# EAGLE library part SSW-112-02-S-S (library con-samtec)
THROUGH-HOLE .025" SQ POST SOCKET Source: Samtec SSW.pdf
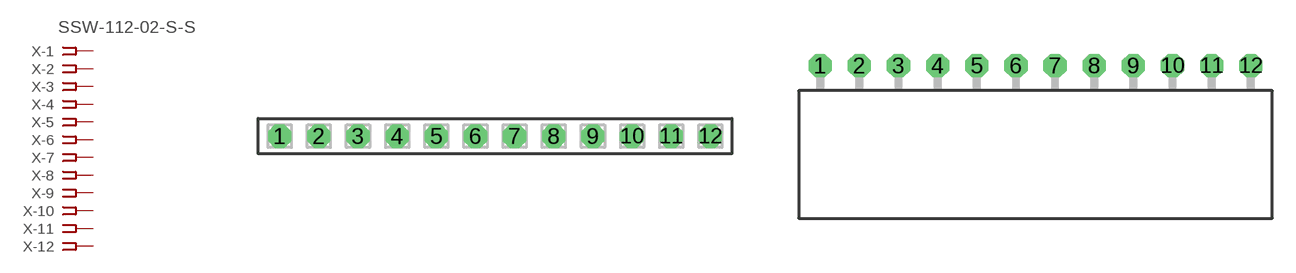
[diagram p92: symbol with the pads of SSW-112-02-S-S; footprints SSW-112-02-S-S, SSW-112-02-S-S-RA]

Designator prefix X; gates -1=FPINV -2=FPIN -3=FPIN -4=FPIN -5=FPIN -6=FPIN -7=FPIN -8=FPIN -9=FPIN -10=FPIN -11=FPIN -12=FPIN

## SSW-112-02-S-S (MPN: SSW-112-02-S-S; OC_FARNELL: unknown; OC_NEWARK: 11P9515)  [SSW-112-02-S-S]
1  -1:1  pas
2  -2:1  pas
3  -3:1  pas
4  -4:1  pas
5  -5:1  pas
6  -6:1  pas
7  -7:1  pas
8  -8:1  pas
9  -9:1  pas
10  -10:1  pas
11  -11:1  pas
12  -12:1  pas

## SSW-112-02-S-S-RA (MPN: SSW-112-02-S-S-RA; OC_FARNELL: unknown; OC_NEWARK: 11P9516)  [SSW-112-02-S-S-RA]
Pads as for SSW-112-02-S-S

## Footprint SSW-112-02-S-S (pad centres in mm)
THROUGH-HOLE .025" SQ POST SOCKET Source: Samtec SSW.pdf
drill 1 pad 1.5 octagon: 1 -13.97,0; 2 -11.43,0; 3 -8.89,0; 4 -6.35,0; 5 -3.81,0; 6 -1.27,0; 7 1.27,0; 8 3.81,0; 9 6.35,0; 10 8.89,0; 11 11.43,0; 12 13.97,0

## Footprint SSW-112-02-S-S-RA (pad centres in mm)
THROUGH-HOLE .025" SQ POST SOCKET Source: Samtec SSW.pdf
drill 1 pad 1.5 octagon: 1 -13.97,1.524; 2 -11.43,1.524; 3 -8.89,1.524; 4 -6.35,1.524; 5 -3.81,1.524; 6 -1.27,1.524; 7 1.27,1.524; 8 3.81,1.524; 9 6.35,1.524; 10 8.89,1.524; 11 11.43,1.524; 12 13.97,1.524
